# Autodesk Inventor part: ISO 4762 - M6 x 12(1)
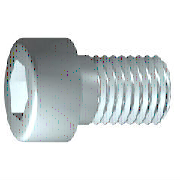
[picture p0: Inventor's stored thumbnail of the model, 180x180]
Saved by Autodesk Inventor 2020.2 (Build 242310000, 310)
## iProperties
Created: 2019-01
Part Number: ISO 4762 - M6 x 12(1)
Material: Acier inoxydable 440C
Description: Vis cylindrique à six pans creux
Document SubType Name: Modeling
Standard: ISO 4762
Designer: Philippe
Standard Revision: Fourth edition 2004-03-01
Standards Organization: ISO
Language: fr-FR
Size Designation: M6 x 12
Categories: <MemberInstance><Categories><Category DisplayName="Visserie" InternalName="e4da775c-781d-43d5-af7c-5136215cf5a6" Mnemonic="FSTN"><Category DisplayName="Vis" Int
Density: 7.75 g/cm^3
Appearance: Semi-poli
IsCustomPart: 0
Author: Philippe
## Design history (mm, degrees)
sketch "Esquisse1"
  geometry: L1 (-1.333, 0)-(12, 0); L2 (12, 0)-(12, 3); L3 (12, 3)-(2.5, 3); L4 (2.5, 3)-(1.886, 3); L5 (1.886, 3)-(0, 3); L6 (0, 3)-(0, 5); L7 (0, 5)-(-6, 5); L8 (-6, 5)-(-6, 2.887); L9 (-6, 2.887)-(-3, 2.887); L10 (-3, 2.887)-(-1.333, 0); L11 (-9.6, 0)-(15.6, 0) reference; L12 (0, -1)-(0, 6) reference; L13 (2.5, 3)-(0, 3)
  constraints: 22 end point, 6 parallel, 2 collinear, 2 perpendicular, 1 horizontal, 1 point on line
  dimensions: "d1" = 9.5 distance from line of L3.end L2 (= GEL); "d2" = 0.61355 distance of L4.end L3.end (computed from GAL); "d3" = 6 distance between parallel lines of L8 L6 (= KOH); "d4" = 3 distance of L8.end L9.end (= INTI); "d5" = 60 deg angle of L10 L1; "d6" = 6 diameter of L3 L1 (= GD); "d7" = 6 diameter of L5 L1 (= BDM); "d8" = 5.7735 diameter of L9 L1 (= 1.1547 x SW); "d9" = 10 diameter of L7 L1 (= KOD); "d26" = 12 distance between parallel lines of L12 L2 (= NLG)
revolve "Corps" sketch "Esquisse1" stored, may be unused: angle "d10" = 90 deg
sketch "Esquisse2"
  geometry: L1 (0, -7)-(0, 7) reference; L2 (-7, 0)-(7, 0) reference; L3 (2.887, 0)-(1.443, -2.5); L4 (1.443, -2.5)-(-1.443, -2.5); L5 (-1.443, -2.5)-(-2.887, 0); L6 (-2.887, 0)-(-1.443, 2.5); L7 (-1.443, 2.5)-(1.443, 2.5); L8 (1.443, 2.5)-(2.887, 0); 2 further points
  constraints: 12 end point, 1 coincident, 1 horizontal alignment, 1 point on line, 12 other
extrude "Rainure" join sketch "Esquisse2" stored distance "d11" = 10; taper "d12" = 0 deg
workplane "Work Plane1"
fillet "Fillet2" dims "d30" = 0.1 (= R)
body "Solid1"
fillet "Congé1" dims "d17" = 0.6 (= RR)
feature "Filetage" dims "d13" = 9.5 (= GEL), "d14" = 0
chamfer "Chanfrein1" distance "d15" = 0.61345 (= -0.5 x SPD + 0.5 x GD); stored, may be unused: second distance "d16" = 0.61345 (= GUL), angle "d27" = 45 deg
other parameters: "GD" = 6 [user parameter; used in 2 equation terms], "NLG" = 12 [user parameter; used in 1 equation term], "GEL" = 9.5 [user parameter; used in 2 equation terms], "KOD" = 10 [user parameter; used in 1 equation term], "KOH" = 6 [user parameter; used in 1 equation term], "INTI" = 3 [user parameter; used in 1 equation term], "GAL" = 0.61345 (= 0.61345 x PTC) [user parameter; used in 1 equation term], "GUL" = 0.61345 (= 0.61345 x PTC) [user parameter; used in 1 equation term], "BDM" = 6 (= NND) [user parameter; used in 1 equation term], "SW" = 5 [user parameter; used in 2 equation terms], "RR" = 0.6 [user parameter; used in 1 equation term], "SPD" = 4.7731 (= NND - 1.2269 x PTC) [user parameter; used in 1 equation term], "d19" = 0, "d28" = 0, "d29" = 0, "R" = 0.1 [user parameter; used in 1 equation term], "TOA" = 30 deg [user parameter], "GD1" = 4.7731 (= THREADDIA - 1.2269 x PTC) [user parameter], "THREADDIA" = 6 [user parameter; used in 1 equation term], "FAWI" = 45 deg [user parameter], "PTC" = 1 [user parameter; used in 5 equation terms], "NND" = 6 [user parameter; used in 2 equation terms], "E0" = 5.775 (= 1.155 x SW) [user parameter]
